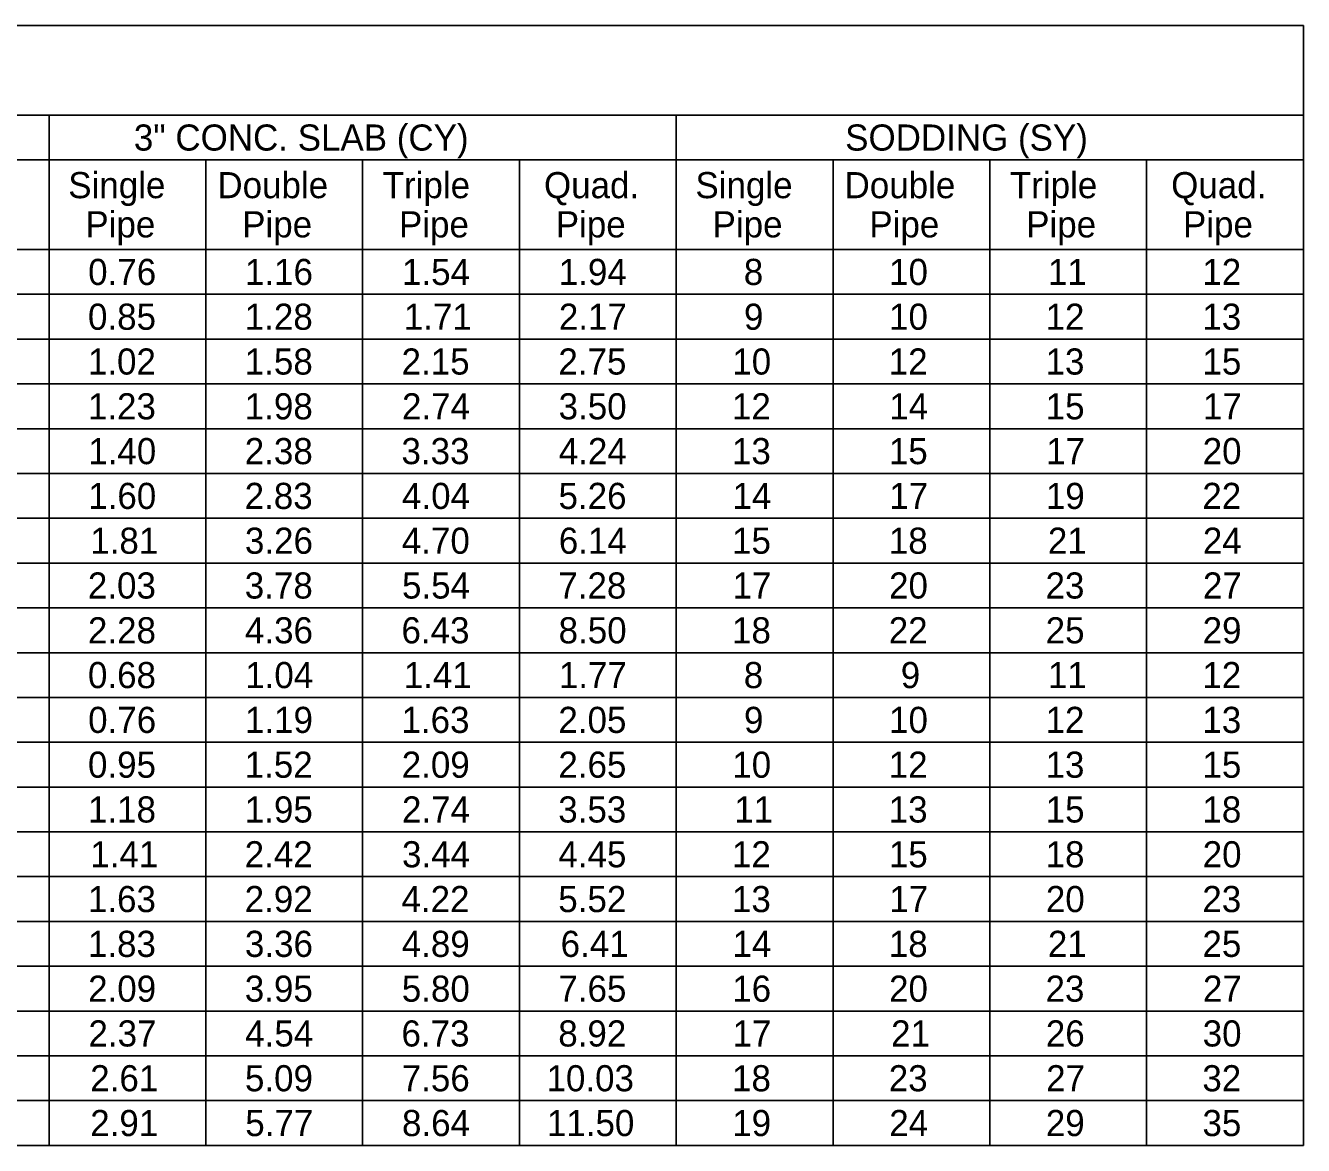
# Model space of a CAD drawing. Extents: x -1.3 to 14.5, y 0 to 8.2.
# Drawn here: x 9.977 to 13.4, y 5.227 to 8.227 of the extents above; entities that cross this region are included whole.
import ezdxf

# ---------------------------------------------------------------- set-up
doc = ezdxf.new("R2010")
doc.units = 0
doc.layers.add('TextNotes', color=7, linetype='Continuous')
doc.layers.add('TextTables', color=7, linetype='Continuous')

msp = doc.modelspace()

# ---------------------------------------------------------------- linework, layer by layer
at = {"layer": 'TextTables'}
msp.add_line((2, 8.2274), (13.4, 8.2274), dxfattribs=at)
for points in [[(13.4, 8.2274), (13.4, 7.9874), (13.4, 7.6274), (13.4, 7.5074), (13.4, 7.3874), (13.4, 7.2674), (13.4, 7.1474), (13.4, 7.0274), (13.4, 6.9074), (13.4, 6.7874), (13.4, 6.6674), (13.4, 6.5474), (13.4, 6.4274), (13.4, 6.3074), (13.4, 6.1874), (13.4, 6.0674), (13.4, 5.9474), (13.4, 5.8274), (13.4, 5.7074), (13.4, 5.5874), (13.4, 5.4674), (13.4, 5.3474), (13.4, 5.2274)], [(13.4, 7.9874), (11.72, 7.9874), (10.04, 7.9874), (8.36, 7.9874), (8, 7.9874), (6.32, 7.9874), (5.96, 7.9874), (5.6, 7.9874), (5.36, 7.9874), (4.88, 7.9874), (4.46, 7.9874), (3.98, 7.9874), (3.56, 7.9874), (3.14, 7.9874), (2.84, 7.9874), (2.54, 7.9874), (2.24, 7.9874), (2, 7.9874)], [(10.04, 7.9874), (10.04, 7.8674), (10.04, 7.6274), (10.04, 7.5074), (10.04, 7.3874), (10.04, 7.2674), (10.04, 7.1474), (10.04, 7.0274), (10.04, 6.9074), (10.04, 6.7874), (10.04, 6.6674), (10.04, 6.5474), (10.04, 6.4274), (10.04, 6.3074), (10.04, 6.1874), (10.04, 6.0674), (10.04, 5.9474), (10.04, 5.8274), (10.04, 5.7074), (10.04, 5.5874), (10.04, 5.4674), (10.04, 5.3474), (10.04, 5.2274)], [(11.72, 7.9874), (11.72, 7.8674), (11.72, 7.6274), (11.72, 7.5074), (11.72, 7.3874), (11.72, 7.2674), (11.72, 7.1474), (11.72, 7.0274), (11.72, 6.9074), (11.72, 6.7874), (11.72, 6.6674), (11.72, 6.5474), (11.72, 6.4274), (11.72, 6.3074), (11.72, 6.1874), (11.72, 6.0674), (11.72, 5.9474), (11.72, 5.8274), (11.72, 5.7074), (11.72, 5.5874), (11.72, 5.4674), (11.72, 5.3474), (11.72, 5.2274)], [(8.36, 7.8674), (9.2, 7.8674), (10.04, 7.8674), (10.46, 7.8674), (10.88, 7.8674), (11.3, 7.8674), (11.72, 7.8674), (12.14, 7.8674), (12.56, 7.8674), (12.98, 7.8674), (13.4, 7.8674)], [(10.46, 7.8674), (10.46, 7.6274), (10.46, 7.5074), (10.46, 7.3874), (10.46, 7.2674), (10.46, 7.1474), (10.46, 7.0274), (10.46, 6.9074), (10.46, 6.7874), (10.46, 6.6674), (10.46, 6.5474), (10.46, 6.4274), (10.46, 6.3074), (10.46, 6.1874), (10.46, 6.0674), (10.46, 5.9474), (10.46, 5.8274), (10.46, 5.7074), (10.46, 5.5874), (10.46, 5.4674), (10.46, 5.3474), (10.46, 5.2274)], [(10.88, 7.8674), (10.88, 7.6274), (10.88, 7.5074), (10.88, 7.3874), (10.88, 7.2674), (10.88, 7.1474), (10.88, 7.0274), (10.88, 6.9074), (10.88, 6.7874), (10.88, 6.6674), (10.88, 6.5474), (10.88, 6.4274), (10.88, 6.3074), (10.88, 6.1874), (10.88, 6.0674), (10.88, 5.9474), (10.88, 5.8274), (10.88, 5.7074), (10.88, 5.5874), (10.88, 5.4674), (10.88, 5.3474), (10.88, 5.2274)], [(11.3, 7.8674), (11.3, 7.6274), (11.3, 7.5074), (11.3, 7.3874), (11.3, 7.2674), (11.3, 7.1474), (11.3, 7.0274), (11.3, 6.9074), (11.3, 6.7874), (11.3, 6.6674), (11.3, 6.5474), (11.3, 6.4274), (11.3, 6.3074), (11.3, 6.1874), (11.3, 6.0674), (11.3, 5.9474), (11.3, 5.8274), (11.3, 5.7074), (11.3, 5.5874), (11.3, 5.4674), (11.3, 5.3474), (11.3, 5.2274)], [(12.14, 7.8674), (12.14, 7.6274), (12.14, 7.5074), (12.14, 7.3874), (12.14, 7.2674), (12.14, 7.1474), (12.14, 7.0274), (12.14, 6.9074), (12.14, 6.7874), (12.14, 6.6674), (12.14, 6.5474), (12.14, 6.4274), (12.14, 6.3074), (12.14, 6.1874), (12.14, 6.0674), (12.14, 5.9474), (12.14, 5.8274), (12.14, 5.7074), (12.14, 5.5874), (12.14, 5.4674), (12.14, 5.3474), (12.14, 5.2274)], [(12.56, 7.8674), (12.56, 7.6274), (12.56, 7.5074), (12.56, 7.3874), (12.56, 7.2674), (12.56, 7.1474), (12.56, 7.0274), (12.56, 6.9074), (12.56, 6.7874), (12.56, 6.6674), (12.56, 6.5474), (12.56, 6.4274), (12.56, 6.3074), (12.56, 6.1874), (12.56, 6.0674), (12.56, 5.9474), (12.56, 5.8274), (12.56, 5.7074), (12.56, 5.5874), (12.56, 5.4674), (12.56, 5.3474), (12.56, 5.2274)], [(12.98, 7.8674), (12.98, 7.6274), (12.98, 7.5074), (12.98, 7.3874), (12.98, 7.2674), (12.98, 7.1474), (12.98, 7.0274), (12.98, 6.9074), (12.98, 6.7874), (12.98, 6.6674), (12.98, 6.5474), (12.98, 6.4274), (12.98, 6.3074), (12.98, 6.1874), (12.98, 6.0674), (12.98, 5.9474), (12.98, 5.8274), (12.98, 5.7074), (12.98, 5.5874), (12.98, 5.4674), (12.98, 5.3474), (12.98, 5.2274)], [(3.98, 7.6274), (4.46, 7.6274), (4.88, 7.6274), (5.36, 7.6274), (5.6, 7.6274), (5.96, 7.6274), (6.32, 7.6274), (6.74, 7.6274), (7.16, 7.6274), (7.58, 7.6274), (8, 7.6274), (8.36, 7.6274), (9.2, 7.6274), (10.04, 7.6274), (10.46, 7.6274), (10.88, 7.6274), (11.3, 7.6274), (11.72, 7.6274), (12.14, 7.6274), (12.56, 7.6274), (12.98, 7.6274), (13.4, 7.6274)], [(3.98, 7.5074), (4.46, 7.5074), (4.88, 7.5074), (5.36, 7.5074), (5.6, 7.5074), (5.96, 7.5074), (6.32, 7.5074), (6.74, 7.5074), (7.16, 7.5074), (7.58, 7.5074), (8, 7.5074), (8.36, 7.5074), (9.2, 7.5074), (10.04, 7.5074), (10.46, 7.5074), (10.88, 7.5074), (11.3, 7.5074), (11.72, 7.5074), (12.14, 7.5074), (12.56, 7.5074), (12.98, 7.5074), (13.4, 7.5074)], [(3.98, 7.3874), (4.46, 7.3874), (4.88, 7.3874), (5.36, 7.3874), (5.6, 7.3874), (5.96, 7.3874), (6.32, 7.3874), (6.74, 7.3874), (7.16, 7.3874), (7.58, 7.3874), (8, 7.3874), (8.36, 7.3874), (9.2, 7.3874), (10.04, 7.3874), (10.46, 7.3874), (10.88, 7.3874), (11.3, 7.3874), (11.72, 7.3874), (12.14, 7.3874), (12.56, 7.3874), (12.98, 7.3874), (13.4, 7.3874)], [(3.98, 7.2674), (4.46, 7.2674), (4.88, 7.2674), (5.36, 7.2674), (5.6, 7.2674), (5.96, 7.2674), (6.32, 7.2674), (6.74, 7.2674), (7.16, 7.2674), (7.58, 7.2674), (8, 7.2674), (8.36, 7.2674), (9.2, 7.2674), (10.04, 7.2674), (10.46, 7.2674), (10.88, 7.2674), (11.3, 7.2674), (11.72, 7.2674), (12.14, 7.2674), (12.56, 7.2674), (12.98, 7.2674), (13.4, 7.2674)], [(3.98, 7.1474), (4.46, 7.1474), (4.88, 7.1474), (5.36, 7.1474), (5.6, 7.1474), (5.96, 7.1474), (6.32, 7.1474), (6.74, 7.1474), (7.16, 7.1474), (7.58, 7.1474), (8, 7.1474), (8.36, 7.1474), (9.2, 7.1474), (10.04, 7.1474), (10.46, 7.1474), (10.88, 7.1474), (11.3, 7.1474), (11.72, 7.1474), (12.14, 7.1474), (12.56, 7.1474), (12.98, 7.1474), (13.4, 7.1474)], [(3.98, 7.0274), (4.46, 7.0274), (4.88, 7.0274), (5.36, 7.0274), (5.6, 7.0274), (5.96, 7.0274), (6.32, 7.0274), (6.74, 7.0274), (7.16, 7.0274), (7.58, 7.0274), (8, 7.0274), (8.36, 7.0274), (9.2, 7.0274), (10.04, 7.0274), (10.46, 7.0274), (10.88, 7.0274), (11.3, 7.0274), (11.72, 7.0274), (12.14, 7.0274), (12.56, 7.0274), (12.98, 7.0274), (13.4, 7.0274)], [(3.98, 6.9074), (4.46, 6.9074), (4.88, 6.9074), (5.36, 6.9074), (5.6, 6.9074), (5.96, 6.9074), (6.32, 6.9074), (6.74, 6.9074), (7.16, 6.9074), (7.58, 6.9074), (8, 6.9074), (8.36, 6.9074), (9.2, 6.9074), (10.04, 6.9074), (10.46, 6.9074), (10.88, 6.9074), (11.3, 6.9074), (11.72, 6.9074), (12.14, 6.9074), (12.56, 6.9074), (12.98, 6.9074), (13.4, 6.9074)], [(3.98, 6.7874), (4.46, 6.7874), (4.88, 6.7874), (5.36, 6.7874), (5.6, 6.7874), (5.96, 6.7874), (6.32, 6.7874), (6.74, 6.7874), (7.16, 6.7874), (7.58, 6.7874), (8, 6.7874), (8.36, 6.7874), (9.2, 6.7874), (10.04, 6.7874), (10.46, 6.7874), (10.88, 6.7874), (11.3, 6.7874), (11.72, 6.7874), (12.14, 6.7874), (12.56, 6.7874), (12.98, 6.7874), (13.4, 6.7874)], [(3.98, 6.6674), (4.46, 6.6674), (4.88, 6.6674), (5.36, 6.6674), (5.6, 6.6674), (5.96, 6.6674), (6.32, 6.6674), (6.74, 6.6674), (7.16, 6.6674), (7.58, 6.6674), (8, 6.6674), (8.36, 6.6674), (9.2, 6.6674), (10.04, 6.6674), (10.46, 6.6674), (10.88, 6.6674), (11.3, 6.6674), (11.72, 6.6674), (12.14, 6.6674), (12.56, 6.6674), (12.98, 6.6674), (13.4, 6.6674)], [(3.98, 6.5474), (4.46, 6.5474), (4.88, 6.5474), (5.36, 6.5474), (5.6, 6.5474), (5.96, 6.5474), (6.32, 6.5474), (6.74, 6.5474), (7.16, 6.5474), (7.58, 6.5474), (8, 6.5474), (8.36, 6.5474), (9.2, 6.5474), (10.04, 6.5474), (10.46, 6.5474), (10.88, 6.5474), (11.3, 6.5474), (11.72, 6.5474), (12.14, 6.5474), (12.56, 6.5474), (12.98, 6.5474), (13.4, 6.5474)], [(3.98, 6.4274), (4.46, 6.4274), (4.88, 6.4274), (5.36, 6.4274), (5.6, 6.4274), (5.96, 6.4274), (6.32, 6.4274), (6.74, 6.4274), (7.16, 6.4274), (7.58, 6.4274), (8, 6.4274), (8.36, 6.4274), (9.2, 6.4274), (10.04, 6.4274), (10.46, 6.4274), (10.88, 6.4274), (11.3, 6.4274), (11.72, 6.4274), (12.14, 6.4274), (12.56, 6.4274), (12.98, 6.4274), (13.4, 6.4274)], [(3.98, 6.3074), (4.46, 6.3074), (4.88, 6.3074), (5.36, 6.3074), (5.6, 6.3074), (5.96, 6.3074), (6.32, 6.3074), (6.74, 6.3074), (7.16, 6.3074), (7.58, 6.3074), (8, 6.3074), (8.36, 6.3074), (9.2, 6.3074), (10.04, 6.3074), (10.46, 6.3074), (10.88, 6.3074), (11.3, 6.3074), (11.72, 6.3074), (12.14, 6.3074), (12.56, 6.3074), (12.98, 6.3074), (13.4, 6.3074)], [(3.98, 6.1874), (4.46, 6.1874), (4.88, 6.1874), (5.36, 6.1874), (5.6, 6.1874), (5.96, 6.1874), (6.32, 6.1874), (6.74, 6.1874), (7.16, 6.1874), (7.58, 6.1874), (8, 6.1874), (8.36, 6.1874), (9.2, 6.1874), (10.04, 6.1874), (10.46, 6.1874), (10.88, 6.1874), (11.3, 6.1874), (11.72, 6.1874), (12.14, 6.1874), (12.56, 6.1874), (12.98, 6.1874), (13.4, 6.1874)], [(3.98, 6.0674), (4.46, 6.0674), (4.88, 6.0674), (5.36, 6.0674), (5.6, 6.0674), (5.96, 6.0674), (6.32, 6.0674), (6.74, 6.0674), (7.16, 6.0674), (7.58, 6.0674), (8, 6.0674), (8.36, 6.0674), (9.2, 6.0674), (10.04, 6.0674), (10.46, 6.0674), (10.88, 6.0674), (11.3, 6.0674), (11.72, 6.0674), (12.14, 6.0674), (12.56, 6.0674), (12.98, 6.0674), (13.4, 6.0674)], [(3.98, 5.9474), (4.46, 5.9474), (4.88, 5.9474), (5.36, 5.9474), (5.6, 5.9474), (5.96, 5.9474), (6.32, 5.9474), (6.74, 5.9474), (7.16, 5.9474), (7.58, 5.9474), (8, 5.9474), (8.36, 5.9474), (9.2, 5.9474), (10.04, 5.9474), (10.46, 5.9474), (10.88, 5.9474), (11.3, 5.9474), (11.72, 5.9474), (12.14, 5.9474), (12.56, 5.9474), (12.98, 5.9474), (13.4, 5.9474)], [(3.98, 5.8274), (4.46, 5.8274), (4.88, 5.8274), (5.36, 5.8274), (5.6, 5.8274), (5.96, 5.8274), (6.32, 5.8274), (6.74, 5.8274), (7.16, 5.8274), (7.58, 5.8274), (8, 5.8274), (8.36, 5.8274), (9.2, 5.8274), (10.04, 5.8274), (10.46, 5.8274), (10.88, 5.8274), (11.3, 5.8274), (11.72, 5.8274), (12.14, 5.8274), (12.56, 5.8274), (12.98, 5.8274), (13.4, 5.8274)], [(3.98, 5.7074), (4.46, 5.7074), (4.88, 5.7074), (5.36, 5.7074), (5.6, 5.7074), (5.96, 5.7074), (6.32, 5.7074), (6.74, 5.7074), (7.16, 5.7074), (7.58, 5.7074), (8, 5.7074), (8.36, 5.7074), (9.2, 5.7074), (10.04, 5.7074), (10.46, 5.7074), (10.88, 5.7074), (11.3, 5.7074), (11.72, 5.7074), (12.14, 5.7074), (12.56, 5.7074), (12.98, 5.7074), (13.4, 5.7074)], [(3.98, 5.5874), (4.46, 5.5874), (4.88, 5.5874), (5.36, 5.5874), (5.6, 5.5874), (5.96, 5.5874), (6.32, 5.5874), (6.74, 5.5874), (7.16, 5.5874), (7.58, 5.5874), (8, 5.5874), (8.36, 5.5874), (9.2, 5.5874), (10.04, 5.5874), (10.46, 5.5874), (10.88, 5.5874), (11.3, 5.5874), (11.72, 5.5874), (12.14, 5.5874), (12.56, 5.5874), (12.98, 5.5874), (13.4, 5.5874)], [(3.98, 5.4674), (4.46, 5.4674), (4.88, 5.4674), (5.36, 5.4674), (5.6, 5.4674), (5.96, 5.4674), (6.32, 5.4674), (6.74, 5.4674), (7.16, 5.4674), (7.58, 5.4674), (8, 5.4674), (8.36, 5.4674), (9.2, 5.4674), (10.04, 5.4674), (10.46, 5.4674), (10.88, 5.4674), (11.3, 5.4674), (11.72, 5.4674), (12.14, 5.4674), (12.56, 5.4674), (12.98, 5.4674), (13.4, 5.4674)], [(3.98, 5.3474), (4.46, 5.3474), (4.88, 5.3474), (5.36, 5.3474), (5.6, 5.3474), (5.96, 5.3474), (6.32, 5.3474), (6.74, 5.3474), (7.16, 5.3474), (7.58, 5.3474), (8, 5.3474), (8.36, 5.3474), (9.2, 5.3474), (10.04, 5.3474), (10.46, 5.3474), (10.88, 5.3474), (11.3, 5.3474), (11.72, 5.3474), (12.14, 5.3474), (12.56, 5.3474), (12.98, 5.3474), (13.4, 5.3474)], [(3.98, 5.2274), (4.46, 5.2274), (4.88, 5.2274), (5.36, 5.2274), (5.6, 5.2274), (5.96, 5.2274), (6.32, 5.2274), (6.74, 5.2274), (7.16, 5.2274), (7.58, 5.2274), (8, 5.2274), (8.36, 5.2274), (8.78, 5.2274), (9.2, 5.2274), (9.62, 5.2274), (10.04, 5.2274), (10.46, 5.2274), (10.88, 5.2274), (11.3, 5.2274), (11.72, 5.2274), (12.14, 5.2274), (12.56, 5.2274), (12.98, 5.2274), (13.4, 5.2274)]]:
    msp.add_lwpolyline(points, dxfattribs=at)

# ---------------------------------------------------------------- texts
at = {"layer": 'TextNotes'}
for s, p in [('3" CONC. SLAB (CY)', (10.2671, 7.8924)), ('SODDING (SY)', (12.1725, 7.8924)), ('Single', (10.0914, 7.7649)), ('Double', (10.4909, 7.7649)), ('Triple', (10.9337, 7.7649)), ('Quad.', (11.3657, 7.7649)), ('Single', (11.7714, 7.7649)), ('Double', (12.1709, 7.7649)), ('Triple', (12.6137, 7.7649)), ('Quad.', (13.0457, 7.7649)), ('Pipe', (10.1373, 7.6599)), ('Pipe', (10.5573, 7.6599)), ('Pipe', (10.9773, 7.6599)), ('Pipe', (11.3973, 7.6599)), ('Pipe', (11.8173, 7.6599)), ('Pipe', (12.2373, 7.6599)), ('Pipe', (12.6573, 7.6599)), ('Pipe', (13.0773, 7.6599)), ('1.54', (10.9854, 7.5324)), ('1.94', (11.4054, 7.5324)), ('8', (11.9009, 7.5324)), ('10', (12.2901, 7.5324)), ('11', (12.7155, 7.5324)), ('1.71', (10.9903, 7.4124)), ('2.17', (11.4056, 7.4124)), ('9', (11.9014, 7.4124)), ('10', (12.2901, 7.4124)), ('2.15', (10.9843, 7.2924)), ('2.75', (11.4043, 7.2924)), ('10', (11.8701, 7.2924)), ('12', (12.2892, 7.2924)), ('2.74', (10.9854, 7.1724)), ('3.50', (11.4049, 7.1724)), ('12', (11.8692, 7.1724)), ('14', (12.2906, 7.1724)), ('15', (12.7095, 7.1724)), ('17', (13.1308, 7.1724)), ('3.33', (10.984, 7.0524)), ('4.24', (11.4054, 7.0524)), ('13', (11.8692, 7.0524)), ('15', (12.2895, 7.0524)), ('17', (12.7108, 7.0524)), ('20', (13.1301, 7.0524)), ('4.04', (10.9854, 6.9324)), ('5.26', (11.4047, 6.9324)), ('14', (11.8706, 6.9324)), ('17', (12.2908, 6.9324)), ('19', (12.71, 6.9324)), ('22', (13.1292, 6.9324)), ('4.70', (10.9849, 6.8124)), ('6.14', (11.4054, 6.8124)), ('15', (11.8695, 6.8124)), ('18', (12.2894, 6.8124)), ('5.54', (10.9854, 6.6924)), ('7.28', (11.4042, 6.6924)), ('17', (11.8708, 6.6924)), ('20', (12.2901, 6.6924)), ('6.43', (10.984, 6.5724)), ('8.50', (11.4049, 6.5724)), ('18', (11.8694, 6.5724)), ('22', (12.2892, 6.5724)), ('25', (12.7095, 6.5724)), ('29', (13.13, 6.5724)), ('0.68', (10.1442, 6.4524)), ('1.04', (10.5654, 6.4524)), ('1.41', (10.9903, 6.4524)), ('1.77', (11.4056, 6.4524)), ('8', (11.9009, 6.4524)), ('9', (12.3214, 6.4524)), ('11', (12.7155, 6.4524)), ('12', (13.1292, 6.4524)), ('0.76', (10.1447, 6.3324)), ('1.19', (10.5647, 6.3324)), ('1.63', (10.984, 6.3324)), ('2.05', (11.4043, 6.3324)), ('9', (11.9014, 6.3324)), ('10', (12.2901, 6.3324)), ('12', (12.7092, 6.3324)), ('13', (13.1292, 6.3324)), ('0.95', (10.1443, 6.2124)), ('1.52', (10.564, 6.2124)), ('2.09', (10.9847, 6.2124)), ('2.65', (11.4043, 6.2124)), ('10', (11.8701, 6.2124)), ('12', (12.2892, 6.2124)), ('13', (12.7092, 6.2124)), ('15', (13.1295, 6.2124)), ('1.18', (10.1442, 6.0924)), ('1.95', (10.5643, 6.0924)), ('2.74', (10.9854, 6.0924)), ('3.53', (11.404, 6.0924)), ('11', (11.8755, 6.0924)), ('13', (12.2892, 6.0924)), ('15', (12.7095, 6.0924)), ('18', (13.1294, 6.0924)), ('1.41', (10.1503, 5.9724)), ('2.42', (10.564, 5.9724)), ('3.44', (10.9854, 5.9724)), ('4.45', (11.4043, 5.9724)), ('12', (11.8692, 5.9724)), ('15', (12.2895, 5.9724)), ('18', (12.7094, 5.9724)), ('20', (13.1301, 5.9724)), ('1.63', (10.144, 5.8524)), ('2.92', (10.564, 5.8524)), ('4.22', (10.984, 5.8524)), ('5.52', (11.404, 5.8524)), ('13', (11.8692, 5.8524)), ('17', (12.2908, 5.8524)), ('20', (12.7101, 5.8524)), ('23', (13.1292, 5.8524)), ('1.83', (10.144, 5.7324)), ('3.36', (10.5647, 5.7324)), ('4.89', (10.9847, 5.7324)), ('6.41', (11.4103, 5.7324)), ('14', (11.8706, 5.7324)), ('18', (12.2894, 5.7324)), ('21', (12.7155, 5.7324)), ('25', (13.1295, 5.7324)), ('2.09', (10.1447, 5.6124)), ('3.95', (10.5643, 5.6124)), ('5.80', (10.9849, 5.6124)), ('7.65', (11.4043, 5.6124)), ('16', (11.87, 5.6124)), ('20', (12.2901, 5.6124)), ('23', (12.7092, 5.6124)), ('27', (13.1308, 5.6124)), ('2.37', (10.1456, 5.4924)), ('4.54', (10.5654, 5.4924)), ('6.73', (10.984, 5.4924)), ('8.92', (11.404, 5.4924)), ('17', (11.8708, 5.4924)), ('21', (12.2955, 5.4924)), ('26', (12.71, 5.4924)), ('30', (13.1301, 5.4924)), ('2.61', (10.1503, 5.3724)), ('5.09', (10.5647, 5.3724)), ('7.56', (10.9847, 5.3724)), ('10.03', (11.3725, 5.3724)), ('18', (11.8694, 5.3724)), ('23', (12.2892, 5.3724)), ('27', (12.7108, 5.3724)), ('32', (13.1292, 5.3724)), ('2.91', (10.1503, 5.2524)), ('5.77', (10.5656, 5.2524)), ('8.64', (10.9854, 5.2524)), ('11.50', (11.3735, 5.2524)), ('19', (11.87, 5.2524)), ('24', (12.2906, 5.2524)), ('29', (12.71, 5.2524)), ('35', (13.1295, 5.2524))]:
    msp.add_text(s, height=0.07, dxfattribs=at).set_placement(p)
for s, p in [('0.76', (10.1447, 7.5324)), ('1.16', (10.5647, 7.5324)), ('12', (13.1292, 7.5324)), ('0.85', (10.1443, 7.4124)), ('1.28', (10.5642, 7.4124)), ('12', (12.7092, 7.4124)), ('13', (13.1292, 7.4124)), ('1.02', (10.144, 7.2924)), ('1.58', (10.5642, 7.2924)), ('13', (12.7092, 7.2924)), ('15', (13.1295, 7.2924)), ('1.23', (10.144, 7.1724)), ('1.98', (10.5642, 7.1724)), ('1.40', (10.1449, 7.0524)), ('2.38', (10.5642, 7.0524)), ('1.60', (10.1449, 6.9324)), ('2.83', (10.564, 6.9324)), ('1.81', (10.1503, 6.8124)), ('3.26', (10.5647, 6.8124)), ('21', (12.7155, 6.8124)), ('24', (13.1306, 6.8124)), ('2.03', (10.144, 6.6924)), ('3.78', (10.5642, 6.6924)), ('23', (12.7092, 6.6924)), ('27', (13.1308, 6.6924)), ('2.28', (10.1442, 6.5724)), ('4.36', (10.5647, 6.5724))]:
    msp.add_text(s, height=0.07, rotation=0, dxfattribs=at).set_placement(p)

doc.saveas('drawing.dxf')
